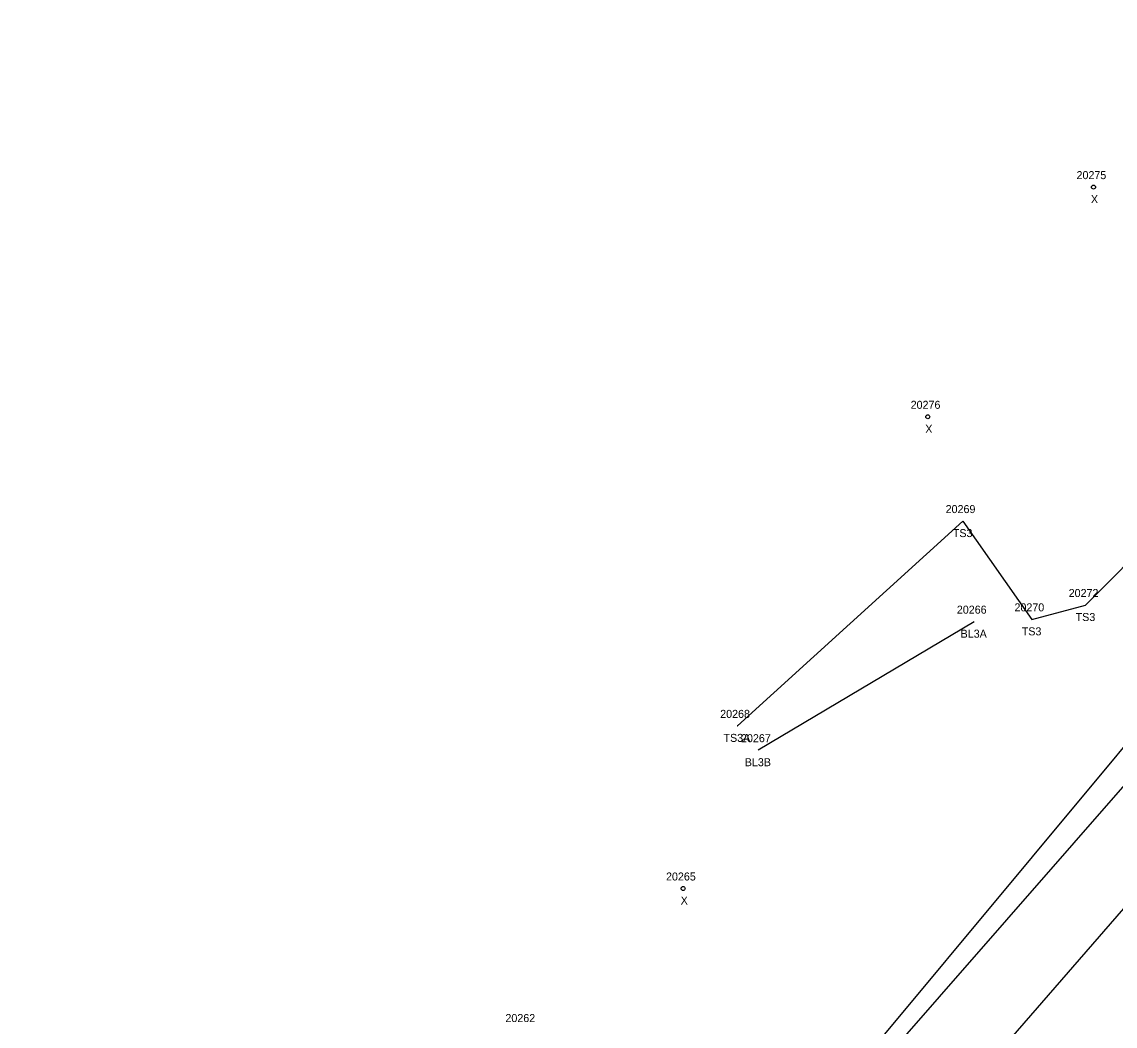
# Model space of a CAD drawing. Extents: x 1813127 to 1814107, y 1178171 to 1179078.
# Drawn here: x 1813803.8 to 1813940.4, y 1178301.3 to 1178426.8 of the extents above; entities that cross this region are included whole.
import ezdxf

# ---------------------------------------------------------------- set-up
doc = ezdxf.new("R2010")
doc.units = 0
for name, color, linetype in [('RD_DTM_BkLn1', 7, 'Continuous'), ('RD_DTM_BkLn2', 7, 'Continuous'), ('RD_EX_Road', 7, 'Continuous'), ('RD_SMD_Locator', 7, 'Continuous'), ('RD_SMD_Misc', 7, 'Continuous')]:
    doc.layers.add(name, color=color, linetype=linetype)

msp = doc.modelspace()

# ---------------------------------------------------------------- linework, layer by layer
at = {"layer": 'RD_DTM_BkLn1'}
msp.add_line((1813922.74, 1178351.86), (1813895.77, 1178335.8), dxfattribs=at)
for points in [[(1814043.03, 1178443.95), (1814035.88, 1178434.61), (1814028.35, 1178424.67), (1814012.24, 1178403.85), (1813982.68, 1178367.11), (1813951.35, 1178327.47), (1813918.15, 1178289.3), (1813882.49, 1178251.63), (1813838.5, 1178201.85)], [(1813889.15, 1178276.31), (1813908.67, 1178296.81), (1813972.77, 1178373.79), (1814000.42, 1178410.19)]]:
    msp.add_lwpolyline(points, dxfattribs=at)
at = {"layer": 'RD_DTM_BkLn2'}
msp.add_lwpolyline([(1813893.16, 1178338.84), (1813921.32, 1178364.43), (1813929.94, 1178352.15), (1813936.66, 1178353.94), (1813964.13, 1178381.53), (1813993.38, 1178417.59), (1814007.74, 1178441.51), (1813972.38, 1178457.8), (1813931.97, 1178507.78), (1813904.27, 1178536.29), (1813860.78, 1178571.07), (1813835.97, 1178602.37), (1813828.98, 1178599.83), (1813813.84, 1178586.1), (1813811.52, 1178575.86), (1813773.95, 1178566.06)], dxfattribs=at)
at = {"layer": 'RD_EX_Road'}
msp.add_lwpolyline([(1813829.87, 1178208.6), (1813830.81, 1178209.56), (1813845.51, 1178227.94), (1813874.69, 1178258.74), (1813910.02, 1178295.38), (1813943.63, 1178333.84), (1813974.31, 1178373.09), (1814001.91, 1178410.56), (1814011.9, 1178425.95), (1814015.58, 1178434.3), (1814016.71, 1178442.08), (1814017.03, 1178447.13), (1814015.19, 1178453.67), (1813986.47, 1178480.85), (1813949.15, 1178515.86), (1813911.94, 1178551.77), (1813875.67, 1178586.1), (1813838.32, 1178620.7), (1813831.51, 1178622), (1813823.35, 1178621.08), (1813815.99, 1178618.51), (1813795.14, 1178605.39)], dxfattribs=at)
at = {"layer": 'RD_SMD_Locator'}
for centre, radius in [((1813937.65, 1178406.16), 0.25), ((1813916.95, 1178377.46), 0.25), ((1813921.32, 1178364.43), 0.001), ((1813936.66, 1178353.94), 0.001), ((1813922.74, 1178351.86), 0.001), ((1813929.94, 1178352.15), 0.001), ((1813893.16, 1178338.84), 0.001), ((1813895.77, 1178335.8), 0.001), ((1813886.39, 1178318.52), 0.25)]:
    msp.add_circle(centre, radius, dxfattribs=at)

# ---------------------------------------------------------------- texts
at = {"layer": 'RD_SMD_Misc'}
for s, p in [('20275', (1813935.53, 1178407.16)), ('X', (1813937.33, 1178404.16)), ('20276', (1813914.81, 1178378.46)), ('X', (1813916.64, 1178375.46)), ('20269', (1813919.18, 1178365.43)), ('TS3', (1813920.08, 1178362.43)), ('20272', (1813934.55, 1178354.94)), ('20270', (1813927.78, 1178353.15)), ('20266', (1813920.58, 1178352.86)), ('TS3', (1813935.42, 1178351.94)), ('BL3A', (1813921.05, 1178349.86)), ('TS3', (1813928.69, 1178350.15)), ('20268', (1813891.02, 1178339.84)), ('TS3A', (1813891.43, 1178336.84)), ('20267', (1813893.62, 1178336.8)), ('BL3B', (1813894.09, 1178333.8)), ('20265', (1813884.25, 1178319.52)), ('X', (1813886.08, 1178316.52)), ('20262', (1813864.19, 1178301.83))]:
    msp.add_text(s, height=1, dxfattribs=at).set_placement(p)

doc.saveas('drawing.dxf')
